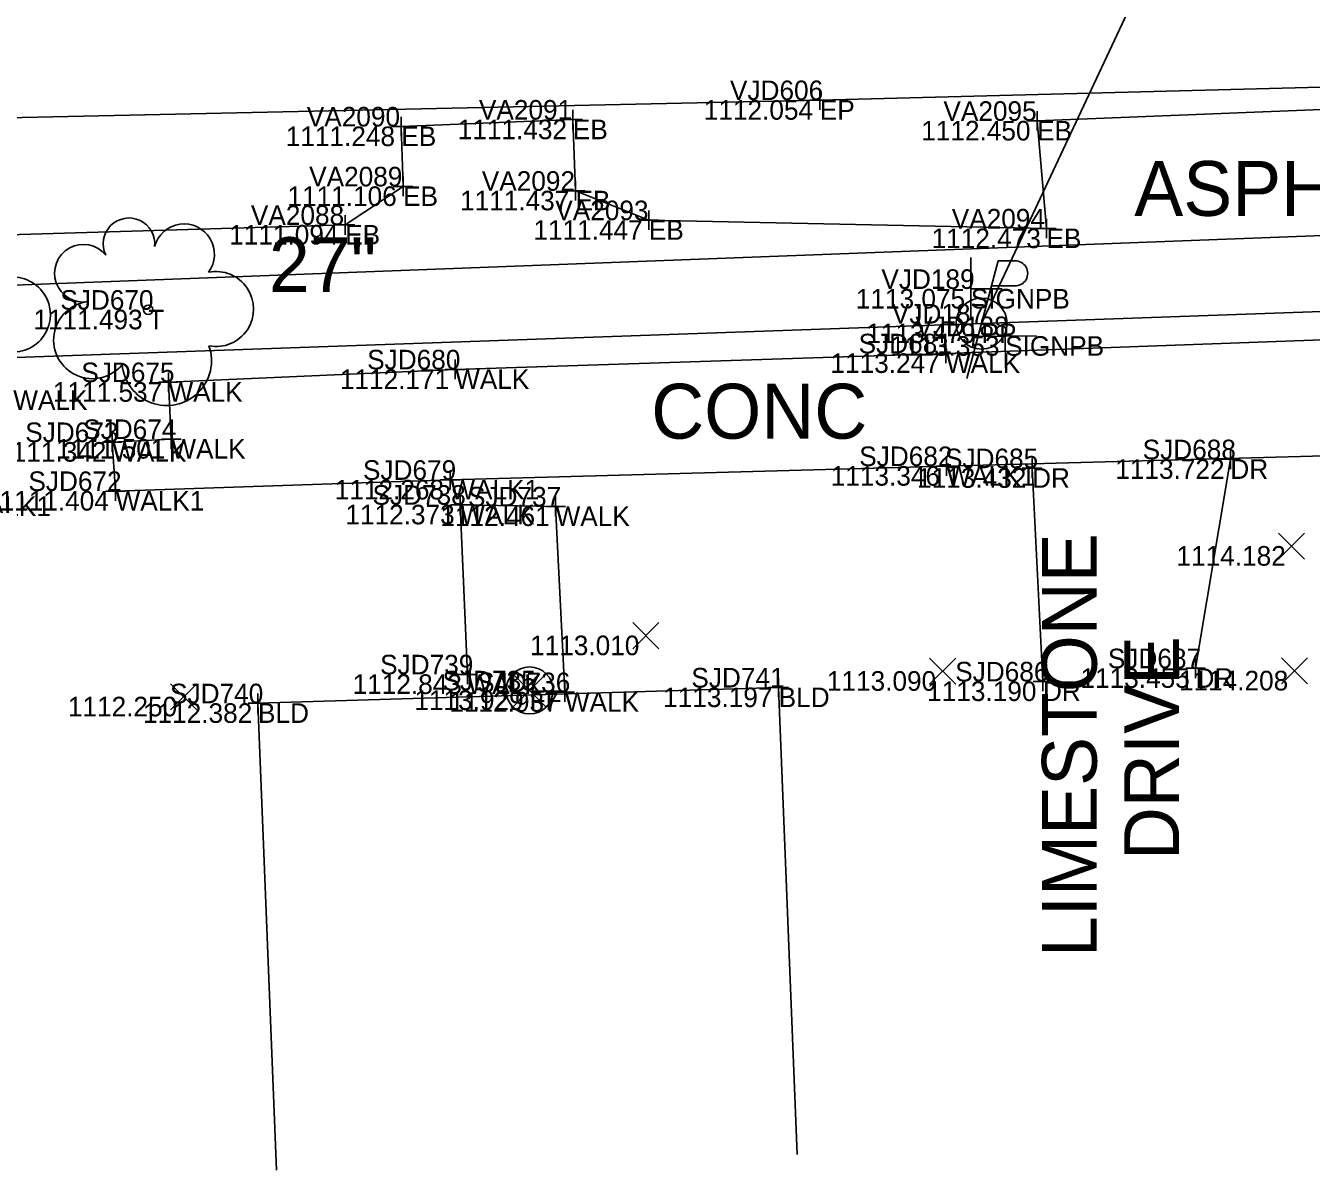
# Model space of a CAD drawing. Extents: x 1629915 to 1630675, y 484401 to 484601.
# Drawn here: x 1630488.9 to 1630554.5, y 484431.1 to 484489.5 of the extents above; entities that cross this region are included whole.
import ezdxf

# ---------------------------------------------------------------- set-up
doc = ezdxf.new("R2010")
doc.units = 0
for name, color, linetype in [('BD_X_Building', 7, 'Continuous'), ('BR_X_Sub_Foot_Object', 7, 'Continuous'), ('PV_X_Driveway', 7, 'Continuous'), ('PV_X_EOP', 7, 'Continuous'), ('PV_X_Shoulder_Aggregate', 7, 'Continuous'), ('PV_X_Walk', 7, 'Continuous'), ('RD_X_RR_Cells', 7, 'Continuous'), ('SN_X_Public', 7, 'Continuous'), ('SV_X_Random_Point', 7, 'Continuous'), ('SV_X_Shot_Marker', 7, 'Continuous'), ('SV_X_Text_Comment', 7, 'Continuous'), ('SV_X_Text_Elevation', 7, 'Continuous'), ('SV_X_Text_Name', 7, 'Continuous'), ('TX_X_20', 7, 'Continuous'), ('UT_X_Electric_Cells', 7, 'Continuous'), ('UT_X_Water', 7, 'Continuous'), ('VG_X_Cells', 7, 'Continuous')]:
    doc.layers.add(name, color=color, linetype=linetype)

msp = doc.modelspace()

# ---------------------------------------------------------------- linework, layer by layer
at = {"layer": 'BD_X_Building'}
for p, q in [((1630528.258, 484431.899), (1630527.312, 484455.742)), ((1630501.689, 484431.093), (1630500.743, 484454.936))]:
    msp.add_line(p, q, dxfattribs=at)
msp.add_lwpolyline([(1630500.746, 484454.936), (1630527.318, 484455.742)], dxfattribs=at)
at = {"layer": 'BR_X_Sub_Foot_Object'}
for p, q in [((1630537.673, 484474.324), (1630560.47, 484522.988)), ((1630537.673, 484474.324), (1630673.622, 484479.085)), ((1630334.981, 484467.226), (1630537.673, 484474.324))]:
    msp.add_line(p, q, dxfattribs=at)
at = {"layer": 'PV_X_Driveway'}
for points in [[(1630540.252, 484466.938), (1630540.808, 484456.052)], [(1630548.591, 484456.724), (1630550.371, 484467.394)]]:
    msp.add_lwpolyline(points, dxfattribs=at)
at = {"layer": 'PV_X_EOP'}
msp.add_lwpolyline([(1630292.708, 484478.565), (1630303.888, 484478.677), (1630360.908, 484480.855), (1630403.548, 484482.238), (1630442.06, 484483.465), (1630486.339, 484484.798), (1630529.418, 484485.732), (1630568.745, 484486.748), (1630610.183, 484487.853), (1630650.035, 484489.089)], dxfattribs=at)
at = {"layer": 'PV_X_Shoulder_Aggregate'}
msp.add_lwpolyline([(1630290.023, 484472.094), (1630316.065, 484472.69), (1630342.812, 484473.661), (1630368.021, 484474.923), (1630386.578, 484475.757), (1630401.756, 484475.856), (1630425.589, 484476.973), (1630451.796, 484477.683), (1630475.368, 484478.476), (1630505.195, 484479.358), (1630508.151, 484481.327), (1630508.061, 484484.385), (1630516.813, 484484.736), (1630516.951, 484481.103), (1630520.694, 484479.601), (1630540.986, 484479.176), (1630540.508, 484484.672), (1630564.841, 484485.646), (1630589.64, 484486.306), (1630613.109, 484486.832)], dxfattribs=at)
at = {"layer": 'PV_X_Walk'}
for p, q in [((1630568.113, 484473.962), (1630535.856, 484472.803)), ((1630535.856, 484472.803), (1630510.805, 484471.984)), ((1630510.805, 484471.984), (1630496.174, 484471.332)), ((1630496.174, 484471.332), (1630496.322, 484468.429)), ((1630496.322, 484468.429), (1630493.305, 484468.273)), ((1630493.305, 484468.273), (1630493.476, 484465.775))]:
    msp.add_line(p, q, dxfattribs=at)
for points in [[(1630493.476, 484465.775), (1630510.562, 484466.345), (1630535.879, 484467.047), (1630568.892, 484467.942), (1630595.477, 484468.584), (1630612.287, 484469.275), (1630612.757, 484463.547), (1630612.783, 484463.442), (1630611.461, 484463.356), (1630611.74, 484459.193), (1630617.565, 484459.663), (1630617.01, 484463.773), (1630616.025, 484463.69), (1630615.968, 484463.775), (1630615.61, 484469.428), (1630634.527, 484469.698), (1630634.521, 484474.409), (1630639.35, 484473.673), (1630639.447, 484470.095), (1630649.394, 484470.376)], [(1630516.406, 484455.504), (1630515.933, 484464.987), (1630511.068, 484465.073), (1630511.437, 484456.413)]]:
    msp.add_lwpolyline(points, dxfattribs=at)
at = {"layer": 'RD_X_RR_Cells'}
for p, q in [((1630515.456, 484454.746), (1630513.759, 484456.443)), ((1630513.759, 484454.746), (1630515.456, 484456.443))]:
    msp.add_line(p, q, dxfattribs=at)
msp.add_circle((1630514.607, 484455.595), 1.2, dxfattribs=at)
at = {"layer": 'SN_X_Public'}
for p, q in [((1630537.125, 484474.491), (1630537.125, 484477.691)), ((1630537.125, 484476.091), (1630538.725, 484476.091)), ((1630537.276, 484473.665), (1630540.476, 484473.695)), ((1630538.876, 484473.68), (1630538.891, 484472.08))]:
    msp.add_line(p, q, dxfattribs=at)
at = {"layer": 'SV_X_Random_Point'}
for p, q in [((1630552.828, 484462.295), (1630554.161, 484463.63)), ((1630552.828, 484463.63), (1630554.161, 484462.295)), ((1630519.877, 484457.725), (1630521.211, 484459.06)), ((1630519.877, 484459.06), (1630521.211, 484457.725)), ((1630535.025, 484455.909), (1630536.359, 484457.244)), ((1630535.025, 484457.244), (1630536.359, 484455.909)), ((1630552.98, 484455.928), (1630554.313, 484457.263)), ((1630552.98, 484457.263), (1630554.313, 484455.928)), ((1630496.288, 484454.602), (1630497.621, 484455.937)), ((1630496.288, 484455.937), (1630497.621, 484454.602))]:
    msp.add_line(p, q, dxfattribs=at)
at = {"layer": 'SV_X_Shot_Marker'}
for p, q in [((1630529.418, 484486.232), (1630529.418, 484485.232)), ((1630528.918, 484485.732), (1630529.918, 484485.732)), ((1630529.418, 484485.732), (1630529.418, 484485.732)), ((1630508.061, 484484.885), (1630508.061, 484483.885)), ((1630516.313, 484484.736), (1630517.313, 484484.736)), ((1630516.813, 484485.236), (1630516.813, 484484.236)), ((1630516.813, 484484.736), (1630516.813, 484484.736)), ((1630540.008, 484484.672), (1630541.008, 484484.672)), ((1630540.508, 484485.172), (1630540.508, 484484.172)), ((1630540.508, 484484.672), (1630540.508, 484484.672)), ((1630507.561, 484484.385), (1630508.561, 484484.385)), ((1630508.061, 484484.385), (1630508.061, 484484.385)), ((1630508.151, 484481.827), (1630508.151, 484480.827)), ((1630516.951, 484481.603), (1630516.951, 484480.603)), ((1630507.651, 484481.327), (1630508.651, 484481.327)), ((1630508.151, 484481.327), (1630508.151, 484481.327)), ((1630516.451, 484481.103), (1630517.451, 484481.103)), ((1630516.951, 484481.103), (1630516.951, 484481.103)), ((1630520.694, 484480.101), (1630520.694, 484479.101)), ((1630505.195, 484479.858), (1630505.195, 484478.858)), ((1630520.194, 484479.601), (1630521.194, 484479.601)), ((1630520.694, 484479.601), (1630520.694, 484479.601)), ((1630540.986, 484479.676), (1630540.986, 484478.676)), ((1630504.695, 484479.358), (1630505.695, 484479.358)), ((1630505.195, 484479.358), (1630505.195, 484479.358)), ((1630540.486, 484479.176), (1630541.486, 484479.176)), ((1630540.986, 484479.176), (1630540.986, 484479.176)), ((1630535.856, 484473.303), (1630535.856, 484472.303)), ((1630510.805, 484472.484), (1630510.805, 484471.484)), ((1630535.356, 484472.803), (1630536.356, 484472.803)), ((1630535.856, 484472.803), (1630535.856, 484472.803)), ((1630496.174, 484471.832), (1630496.174, 484470.832)), ((1630510.305, 484471.984), (1630511.305, 484471.984)), ((1630510.805, 484471.984), (1630510.805, 484471.984)), ((1630495.674, 484471.332), (1630496.674, 484471.332)), ((1630496.174, 484471.332), (1630496.174, 484471.332)), ((1630496.322, 484468.929), (1630496.322, 484467.929)), ((1630492.805, 484468.273), (1630493.805, 484468.273)), ((1630493.305, 484468.773), (1630493.305, 484467.773)), ((1630493.305, 484468.273), (1630493.305, 484468.273)), ((1630495.822, 484468.429), (1630496.822, 484468.429)), ((1630496.322, 484468.429), (1630496.322, 484468.429)), ((1630550.371, 484467.894), (1630550.371, 484466.894)), ((1630535.379, 484467.047), (1630536.379, 484467.047)), ((1630535.879, 484467.547), (1630535.879, 484466.547)), ((1630535.879, 484467.047), (1630535.879, 484467.047)), ((1630539.752, 484466.938), (1630540.752, 484466.938)), ((1630540.252, 484467.438), (1630540.252, 484466.438)), ((1630540.252, 484466.938), (1630540.252, 484466.938)), ((1630549.871, 484467.394), (1630550.871, 484467.394)), ((1630550.371, 484467.394), (1630550.371, 484467.394)), ((1630493.476, 484466.275), (1630493.476, 484465.275)), ((1630510.062, 484466.345), (1630511.062, 484466.345)), ((1630510.562, 484466.845), (1630510.562, 484465.845)), ((1630510.562, 484466.345), (1630510.562, 484466.345)), ((1630492.976, 484465.775), (1630493.976, 484465.775)), ((1630493.476, 484465.775), (1630493.476, 484465.775)), ((1630510.568, 484465.073), (1630511.568, 484465.073)), ((1630511.068, 484465.573), (1630511.068, 484464.573)), ((1630511.068, 484465.073), (1630511.068, 484465.073)), ((1630515.433, 484464.987), (1630516.433, 484464.987)), ((1630515.933, 484465.487), (1630515.933, 484464.487)), ((1630515.933, 484464.987), (1630515.933, 484464.987)), ((1630548.591, 484457.224), (1630548.591, 484456.224)), ((1630510.937, 484456.413), (1630511.937, 484456.413)), ((1630511.437, 484456.913), (1630511.437, 484455.913)), ((1630511.437, 484456.413), (1630511.437, 484456.413)), ((1630540.808, 484456.552), (1630540.808, 484455.552)), ((1630548.091, 484456.724), (1630549.091, 484456.724)), ((1630548.591, 484456.724), (1630548.591, 484456.724)), ((1630516.406, 484456.004), (1630516.406, 484455.004)), ((1630527.318, 484456.242), (1630527.318, 484455.242)), ((1630540.308, 484456.052), (1630541.308, 484456.052)), ((1630540.808, 484456.052), (1630540.808, 484456.052)), ((1630500.746, 484455.436), (1630500.746, 484454.436)), ((1630515.906, 484455.504), (1630516.906, 484455.504)), ((1630516.406, 484455.504), (1630516.406, 484455.504)), ((1630526.818, 484455.742), (1630527.818, 484455.742)), ((1630527.318, 484455.742), (1630527.318, 484455.742)), ((1630500.246, 484454.936), (1630501.246, 484454.936)), ((1630500.746, 484454.936), (1630500.746, 484454.936))]:
    msp.add_line(p, q, dxfattribs=at)
at = {"layer": 'UT_X_Electric_Cells'}
for p, q in [((1630538.529, 484477.524), (1630536.923, 484471.524)), ((1630538.529, 484477.524), (1630539.379, 484477.524)), ((1630538.188, 484476.249), (1630539.379, 484476.249))]:
    msp.add_line(p, q, dxfattribs=at)
msp.add_circle((1630537.673, 484474.324), 1.3, dxfattribs=at)
msp.add_arc((1630539.392, 484476.887), 0.638, 268.8767, 91.1233, dxfattribs=at)
at = {"layer": 'UT_X_Water'}
msp.add_line((1630348.219, 484470.927), (1630675.08, 484483.409), dxfattribs=at)
at = {"layer": 'VG_X_Cells'}
msp.add_circle((1630495.145, 484475.03), 0.24, dxfattribs=at)
for centre, radius, start, end in [((1630494.161, 484478.397), 1.317, 354.0047, 205.97412), ((1630496.971, 484477.859), 1.553, 323.82996, 165.0376), ((1630491.835, 484476.894), 1.471, 39.06254, 279.54124), ((1630498.605, 484475.065), 1.915, 259.14531, 101.45961), ((1630488.235, 484474.781), 1.915, 259.14531, 101.45961), ((1630492.291, 484473.481), 1.974, 96.17219, 320.57371), ((1630496.091, 484472.424), 2.284, 184.94757, 19.45715)]:
    msp.add_arc(centre, radius, start, end, dxfattribs=at)

# ---------------------------------------------------------------- texts
at = {"layer": 'SV_X_Text_Comment'}
for s, p in [('EP', (1630529.418, 484484.732)), ('EB', (1630516.813, 484483.736)), ('EB', (1630540.508, 484483.672)), ('EB', (1630508.061, 484483.385)), ('EB', (1630508.151, 484480.327)), ('EB', (1630516.951, 484480.103)), ('EB', (1630520.694, 484478.601)), ('EB', (1630505.195, 484478.358)), ('EB', (1630540.986, 484478.176)), ('SIGNPB', (1630537.125, 484475.091)), ('T', (1630495.145, 484474.03)), ('PP', (1630537.673, 484473.324)), ('SIGNPB', (1630538.876, 484472.68)), ('WALK', (1630535.856, 484471.803)), ('WALK', (1630510.805, 484470.984)), ('WALK', (1630488.254, 484469.917)), ('WALK', (1630496.174, 484470.332)), ('WALK', (1630493.305, 484467.273)), ('WALK', (1630496.322, 484467.429)), ('WALK1', (1630535.879, 484466.047)), ('DR', (1630540.252, 484465.938)), ('DR', (1630550.371, 484466.394)), ('WALK1', (1630510.562, 484465.345)), ('WALK1', (1630493.476, 484464.775)), ('WALK1', (1630485.646, 484464.495)), ('WALK', (1630511.068, 484464.073)), ('WALK', (1630515.933, 484463.987)), ('WALK', (1630511.437, 484455.413)), ('DR', (1630548.591, 484455.724)), ('DR', (1630540.808, 484455.052)), ('FF', (1630514.607, 484454.595)), ('WALK', (1630516.406, 484454.504)), ('BLD', (1630527.318, 484454.742)), ('BLD', (1630500.746, 484453.936))]:
    msp.add_text(s, height=1, dxfattribs=at).set_placement(p)
at = {"layer": 'SV_X_Text_Elevation'}
for s, p in [('1112.054', (1630523.498, 484484.732)), ('1111.432', (1630510.942, 484483.736)), ('1112.450', (1630534.596, 484483.672)), ('1111.248', (1630502.162, 484483.385)), ('1111.106', (1630502.249, 484480.327)), ('1111.437', (1630511.057, 484480.103)), ('1111.094', (1630499.275, 484478.358)), ('1111.447', (1630514.8, 484478.601)), ('1112.473', (1630535.124, 484478.176)), ('1113.075', (1630531.257, 484475.091)), ('1111.493', (1630489.283, 484474.03)), ('1113.479', (1630531.791, 484473.324)), ('1113.353', (1630533.014, 484472.68)), ('1113.247', (1630529.962, 484471.803)), ('1112.171', (1630504.925, 484470.984)), ('1111.537', (1630490.28, 484470.332)), ('1111.342', (1630487.434, 484467.273)), ('1111.501', (1630490.442, 484467.429)), ('1113.346', (1630529.976, 484466.047)), ('1113.432', (1630534.381, 484465.938)), ('1113.722', (1630544.499, 484466.394)), ('1112.268', (1630504.663, 484465.345)), ('1111.404', (1630487.556, 484464.775)), ('1112.373', (1630505.206, 484464.073)), ('1112.461', (1630510.053, 484463.987)), ('1114.182', (1630547.623, 484461.963)), ('1113.010', (1630514.632, 484457.392)), ('1112.843', (1630505.575, 484455.413)), ('1113.090', (1630529.78, 484455.577)), ('1113.455', (1630542.722, 484455.724)), ('1114.208', (1630547.748, 484455.595)), ('1113.197', (1630521.424, 484454.742)), ('1113.190', (1630534.897, 484455.052)), ('1112.250', (1630491.043, 484454.27)), ('1113.929', (1630508.726, 484454.595)), ('1112.937', (1630510.512, 484454.504)), ('1112.382', (1630494.875, 484453.936))]:
    msp.add_text(s, height=1, dxfattribs=at).set_placement(p)
at = {"layer": 'SV_X_Text_Name'}
for s, p in [('VJD606', (1630524.834, 484485.732)), ('VA2090', (1630503.237, 484484.385)), ('VA2091', (1630512.021, 484484.736)), ('VA2095', (1630535.727, 484484.672)), ('VA2089', (1630503.357, 484481.327)), ('VA2092', (1630512.167, 484481.103)), ('VA2088', (1630500.384, 484479.358)), ('VA2093', (1630515.919, 484479.601)), ('VA2094', (1630536.153, 484479.176)), ('VJD189', (1630532.562, 484476.091)), ('SJD670', (1630490.657, 484475.03)), ('VJD187', (1630533.097, 484474.324)), ('VJD188', (1630534.295, 484473.68)), ('SJD681', (1630531.4, 484472.803)), ('SJD680', (1630506.317, 484471.984)), ('SJD675', (1630491.729, 484471.332)), ('SJD673', (1630488.867, 484468.273)), ('SJD674', (1630491.825, 484468.429)), ('SJD688', (1630545.896, 484467.394)), ('SJD682', (1630531.431, 484467.047)), ('SJD685', (1630535.807, 484466.938)), ('SJD679', (1630506.103, 484466.345)), ('SJD672', (1630489.028, 484465.775)), ('SJD738', (1630506.593, 484465.073)), ('SJD737', (1630511.463, 484464.987)), ('SJD687', (1630544.12, 484456.724)), ('SJD739', (1630506.978, 484456.413)), ('SJD686', (1630536.329, 484456.052)), ('SJD735', (1630510.162, 484455.595)), ('SJD736', (1630511.927, 484455.504)), ('SJD741', (1630522.862, 484455.742)), ('SJD740', (1630496.258, 484454.936))]:
    msp.add_text(s, height=1, dxfattribs=at).set_placement(p)
at = {"layer": 'TX_X_20'}
for s, rotation, p in [('ASPHALT', 360, (1630545.47, 484479.822)), ('LIMESTONE', 90, (1630543.553, 484441.977)), ('DRIVE', 90, (1630547.753, 484446.928))]:
    msp.add_text(s, height=2.8, rotation=rotation, dxfattribs=at).set_placement(p)
for s, p in [('27"', (1630501.305, 484475.931)), ('CONC', (1630520.815, 484468.449))]:
    msp.add_text(s, height=2.8, dxfattribs=at).set_placement(p)

doc.saveas('drawing.dxf')
